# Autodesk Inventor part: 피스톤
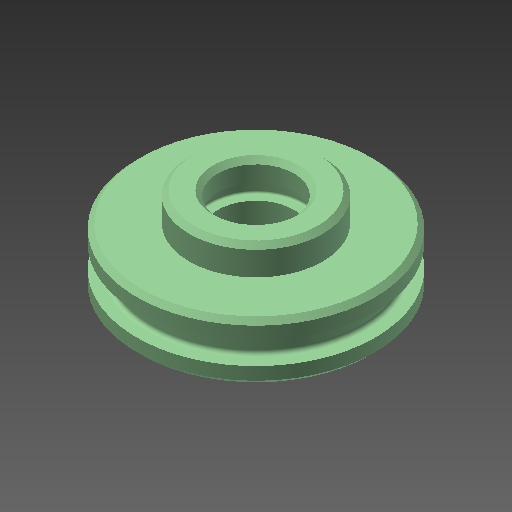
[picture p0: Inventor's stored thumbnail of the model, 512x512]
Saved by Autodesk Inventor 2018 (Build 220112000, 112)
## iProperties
Created: 2023-03
Part Number: 피스톤
Material: 강철, 연강
Document SubType Name: Modeling
Designer: mdu-01
Density: 1 g/cm^3
Appearance: 기본값(1)
Author: mdu-01
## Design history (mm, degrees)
sketch "스케치1"
  geometry: L1 (0, 0)-(13, 0); L2 (14, 1)-(14, 6); L3 (14, 6)-(24, 6); L4 (25, 7)-(25, 9.65); L5 (25, 9.65)-(22.8, 9.65); L6 (22, 10.45)-(22, 13.55); L7 (22.8, 14.35)-(25, 14.35); L8 (25, 14.35)-(25, 17); L9 (24, 18)-(14, 18); L10 (14, 18)-(14, 23); L11 (13, 24)-(9, 24); L12 (8, 12)-(0, 12); L13 (0, 12)-(0, 0); L14 (22, 12)-(25, 12); L15 (9, 24)-(8, 23); L16 (14, 23)-(13, 24); L17 (25, 17)-(24, 18); L18 (24, 6)-(25, 7); L19 (13, 0)-(14, 1); L20 (8, 19.6)-(9.6, 19.6); L21 (10, 19.2)-(10, 16.8); L22 (9.6, 16.4)-(8, 16.4); L23 (8, 23)-(8, 19.6); L24 (8, 16.4)-(8, 12); A1 r 0.8 centre (22.8, 10.45) between (22, 10.45) and (22.8, 9.65); A2 r 0.8 centre (22.8, 13.55) between (22.8, 14.35) and (22, 13.55); A3 r 0.4 centre (9.6, 19.2) between (10, 19.2) and (9.6, 19.6); A4 r 0.4 centre (9.6, 16.8) between (9.6, 16.4) and (10, 16.8); 6 further points
  constraints: 48 end point, 11 parallel, 11 point on line, 8 perpendicular, 8 point on circle, 8 tangent, 4 centre point, 3 collinear, 2 equal radius, 2 midpoint, 1 horizontal, 1 other
  dimensions: "d0" = 50 diameter of L4 L13; "d2" = 0.8 radius of A1; "d3" = 24 distance between parallel lines of L11 L1; "d4" = 6 distance between parallel lines of L9 L11; "d5" = 4.7 distance between parallel lines of L5 L7; "d6" = 6 distance between parallel lines of L3 L1; "d7" = 44 diameter of L6 L13; "d8" = 28 diameter of L2 L13; "d10" = 12 distance between parallel lines of L12 L11; "d11" = 1 distance of L11.end point (8, 24); "d12" = 1 distance of L15.end point (8, 24) (= d11); "d13" = 1 distance of L10.end point (14, 24) (= d11); "d14" = 1 distance of L11.start point (14, 24) (= d13); "d15" = 1 distance of L8.end point (25, 18) (= d11); "d16" = 1 distance of L9.start point (25, 18) (= d15); "d17" = 1 distance of L3.end point (25, 6) (= d11); "d18" = 1 distance of L4.start point (25, 6) (= d17); "d19" = 1 distance of L1.end point (14, 0) (= d11); "d20" = 1 distance of L2.start point (14, 0) (= d19); "d31" = 16 diameter of L23 L13; "d32" = 0.4 radius of A3; "d33" = 6 distance from line of point (10, 18) L11; "d34" = 3.2 distance between parallel lines of L22 L20; "d35" = 20 diameter of L21 L13
revolve "회전1" sketch "스케치1" stored, may be unused: angle "d21" = 90 deg
hole "구멍1" diameter "d24" = 6.6; stored, may be unused: countersink angle "d28" = 90 deg, drill point angle "d30" = 118 deg; dims "d25" = 6, "d26" = 11, "d27" = 8, "d29" = 8, "d36" = 10, "d37" = 10
node "솔리드1"
other parameters: "d9" = 16
